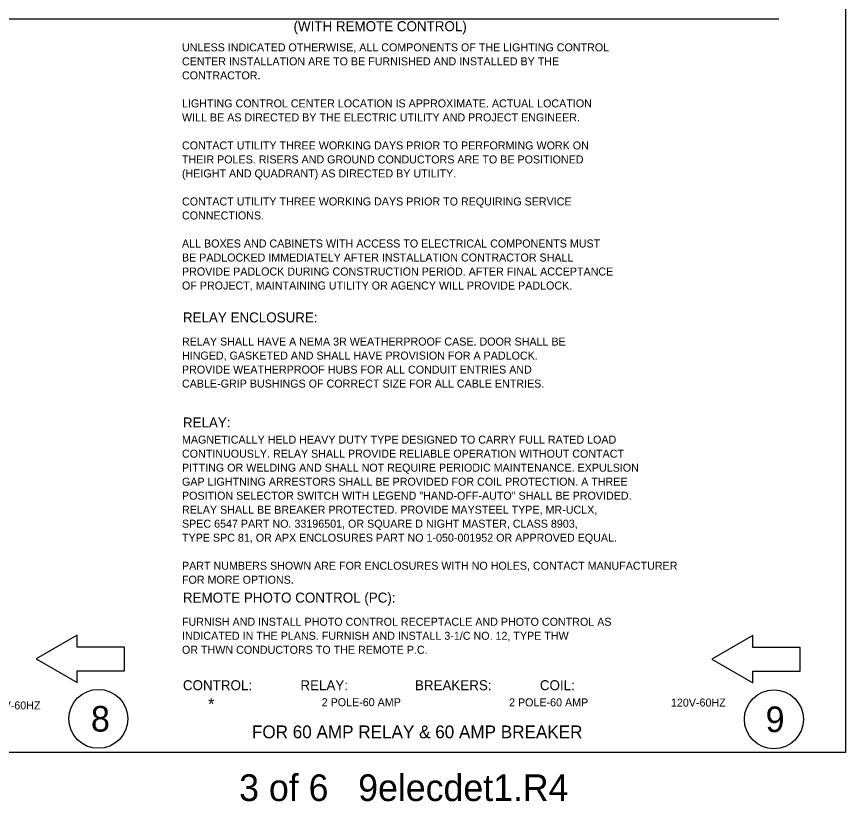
# Model space of a CAD drawing. Extents: x 100006 to 118406, y 96592 to 102182.
# Drawn here: x 112163 to 113406, y 99813 to 100989 of the extents above; entities that cross this region are included whole.
import ezdxf

# ---------------------------------------------------------------- set-up
doc = ezdxf.new("R2010")
doc.units = 0
for name, color, linetype in [('Default', 7, 'Continuous'), ('Level 1', 7, 'Continuous'), ('Level 7', 7, 'Continuous'), ('Level 9', 7, 'Continuous'), ('RD Standard Plans Active', 7, 'Continuous')]:
    doc.layers.add(name, color=color, linetype=linetype)

msp = doc.modelspace()

# ---------------------------------------------------------------- linework, layer by layer
at = {"layer": 'Default'}
msp.add_lwpolyline([(110206.1, 102085.7), (113405.8, 102085.7), (113405.8, 99886.1), (110206.1, 99886.1)], close=True, dxfattribs=at)
at = {"layer": 'Level 1'}
msp.add_line((110305.9, 100985.9), (113305.9, 100985.9), dxfattribs=at)
at = {"layer": 'Level 9'}
for points in [[(112192.9, 100026.5), (112254.4, 99991), (112254.4, 100008.8), (112325.3, 100008.8), (112325.3, 100044.2), (112254.4, 100044.2), (112254.4, 100062)], [(113205.4, 100025.9), (113266.9, 99990.4), (113266.9, 100008.1), (113337.8, 100008.1), (113337.8, 100043.6), (113266.9, 100043.6), (113266.9, 100061.3)]]:
    msp.add_lwpolyline(points, close=True, dxfattribs=at)
for centre in [(112286, 99936.6), (113298.5, 99936)]:
    msp.add_circle(centre, 44.2, dxfattribs=at)

# ---------------------------------------------------------------- texts
at = {"layer": 'Level 7'}
for s, height, p in [('(WITH REMOTE CONTROL)', 15, (112578.6, 100967.3)), ('UNLESS INDICATED OTHERWISE, ALL COMPONENTS OF THE LIGHTING CONTROL', 12, (112411.4, 100937.1)), ('CENTER INSTALLATION ARE TO BE FURNISHED AND INSTALLED BY THE', 12, (112411.4, 100916.1)), ('CONTRACTOR.', 12, (112411.4, 100895.1)), ('LIGHTING CONTROL CENTER LOCATION IS APPROXIMATE. ACTUAL LOCATION', 12, (112411.4, 100853.1)), ('WILL BE AS DIRECTED BY THE ELECTRIC UTILITY AND PROJECT ENGINEER.', 12, (112411.4, 100832.1)), ('CONTACT UTILITY THREE WORKING DAYS PRIOR TO PERFORMING WORK ON', 12, (112411.4, 100790.1)), ('THEIR POLES. RISERS AND GROUND CONDUCTORS ARE TO BE POSITIONED', 12, (112411.4, 100769.1)), ('(HEIGHT AND QUADRANT) AS DIRECTED BY UTILITY.', 12, (112411.4, 100748.1)), ('CONTACT UTILITY THREE WORKING DAYS PRIOR TO REQUIRING SERVICE', 12, (112411.4, 100706.1)), ('CONNECTIONS.', 12, (112411.4, 100685.1)), ('ALL BOXES AND CABINETS WITH ACCESS TO ELECTRICAL COMPONENTS MUST', 12, (112411.4, 100643.1)), ('BE PADLOCKED IMMEDIATELY AFTER INSTALLATION CONTRACTOR SHALL', 12, (112411.4, 100622.1)), ('PROVIDE PADLOCK DURING CONSTRUCTION PERIOD. AFTER FINAL ACCEPTANCE', 12, (112411.4, 100601.1)), ('OF PROJECT, MAINTAINING UTILITY OR AGENCY WILL PROVIDE PADLOCK.', 12, (112411.4, 100580.1)), ('RELAY ENCLOSURE:', 15, (112412.8, 100530.8)), ('RELAY SHALL HAVE A NEMA 3R WEATHERPROOF CASE. DOOR SHALL BE', 12, (112411.4, 100496.1)), ('HINGED, GASKETED AND SHALL HAVE PROVISION FOR A PADLOCK.', 12, (112411.4, 100475.1)), ('PROVIDE WEATHERPROOF HUBS FOR ALL CONDUIT ENTRIES AND', 12, (112411.4, 100454.1)), ('CABLE-GRIP BUSHINGS OF CORRECT SIZE FOR ALL CABLE ENTRIES.', 12, (112411.4, 100433.1)), ('RELAY:', 15, (112412.8, 100373.3)), ('MAGNETICALLY HELD HEAVY DUTY TYPE DESIGNED TO CARRY FULL RATED LOAD ', 12, (112411.4, 100349.1)), ('CONTINUOUSLY. RELAY SHALL PROVIDE RELIABLE OPERATION WITHOUT CONTACT ', 12, (112411.4, 100328.1)), ('PITTING OR WELDING AND SHALL NOT REQUIRE PERIODIC MAINTENANCE. EXPULSION ', 12, (112411.4, 100307.1)), ('GAP LIGHTNING ARRESTORS SHALL BE PROVIDED FOR COIL PROTECTION. A THREE ', 12, (112411.4, 100286.1)), ('POSITION SELECTOR SWITCH WITH LEGEND "HAND-OFF-AUTO" SHALL BE PROVIDED.  ', 12, (112411.4, 100265.1)), ('RELAY SHALL BE BREAKER PROTECTED. PROVIDE MAYSTEEL TYPE, MR-UCLX,', 12, (112411.4, 100244.1)), ('SPEC 6547 PART NO. 33196501, OR SQUARE D NIGHT MASTER, CLASS 8903,', 12, (112411.4, 100223.1)), ('TYPE SPC 81, OR APX ENCLOSURES PART NO 1-050-001952 OR APPROVED EQUAL.', 12, (112411.4, 100202.1)), ('PART NUMBERS SHOWN ARE FOR ENCLOSURES WITH NO HOLES, CONTACT MANUFACTURER', 12, (112411.4, 100160.1)), ('FOR MORE OPTIONS.', 12, (112411.4, 100139.1)), ('REMOTE PHOTO CONTROL (PC):', 15, (112412.8, 100110.8)), ('FURNISH AND INSTALL PHOTO CONTROL RECEPTACLE AND PHOTO CONTROL AS', 12, (112411.4, 100076.1)), ('INDICATED IN THE PLANS. FURNISH AND INSTALL 3-1/C NO. 12, TYPE THW ', 12, (112411.4, 100055.1)), ('OR THWN CONDUCTORS TO THE REMOTE P.C. ', 12, (112411.4, 100034.1)), ('CONTROL:             RELAY:                  BREAKERS:             COIL:', 15, (112412.8, 99979.5)), ('*', 18, (112450.6, 99949.8)), ('2 POLE-60 AMP', 12, (112620.8, 99955.5)), ('2 POLE-60 AMP', 12, (112901.6, 99955.3)), ('120V-60HZ', 12, (113144.3, 99955)), ('120V-60HZ', 12, (112117.3, 99950.7))]:
    msp.add_text(s, height=height, dxfattribs=at).set_placement(p)
at = {"layer": 'Level 9'}
for s, height, p in [('8', 38.3, (112274.9, 99917.5)), ('9', 38.3, (113286.1, 99916.8)), ('FOR 60 AMP RELAY & 60 AMP BREAKER', 19.156, (112516.2, 99907.5))]:
    msp.add_text(s, height=height, dxfattribs=at).set_placement(p)
at = {"layer": 'RD Standard Plans Active'}
msp.add_text('     3 of 6   9elecdet1.R4', height=40, dxfattribs=at).set_placement((112422.8, 99813.4))

doc.saveas('drawing.dxf')
